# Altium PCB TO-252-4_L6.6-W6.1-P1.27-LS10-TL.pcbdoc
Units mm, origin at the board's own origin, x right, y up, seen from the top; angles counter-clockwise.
Board outline 23.63 x 19.35 mm, 2 copper layers (Top Layer, Bottom Layer), stack 0 mm thick; 1 components, 0 nets, 5 pads, 0 vias.
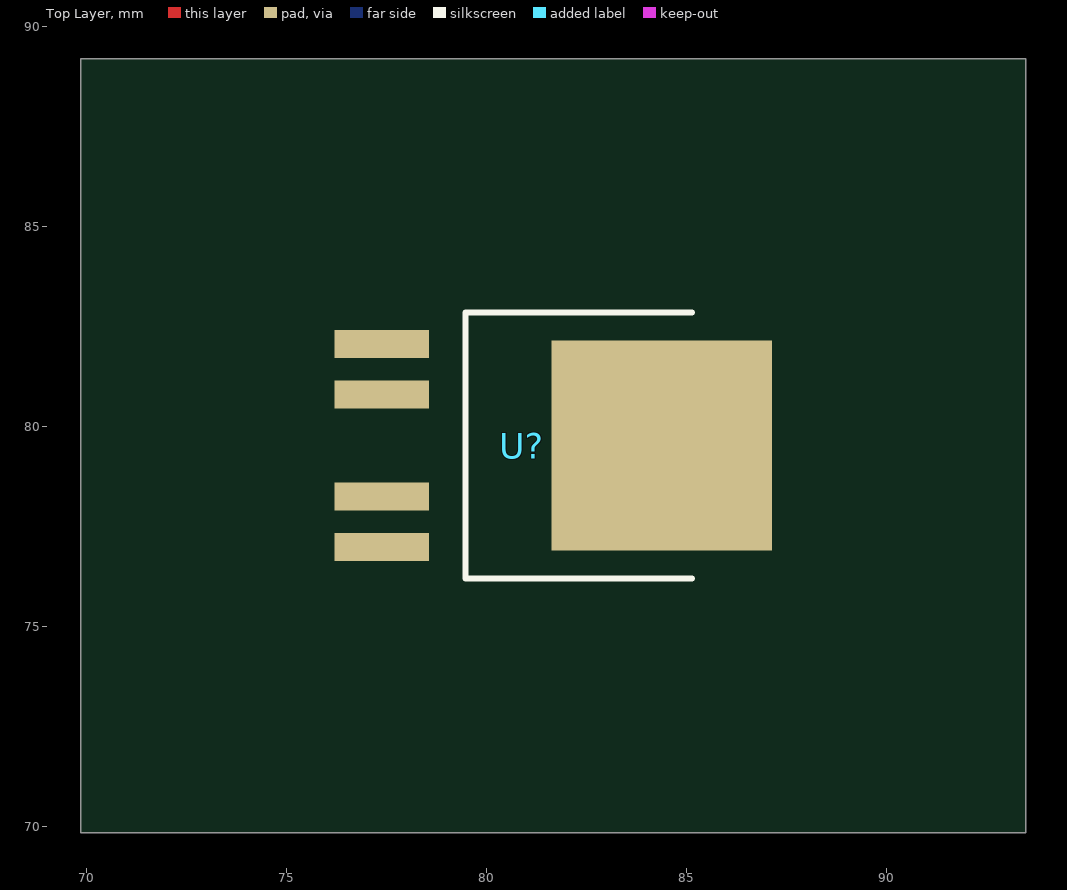
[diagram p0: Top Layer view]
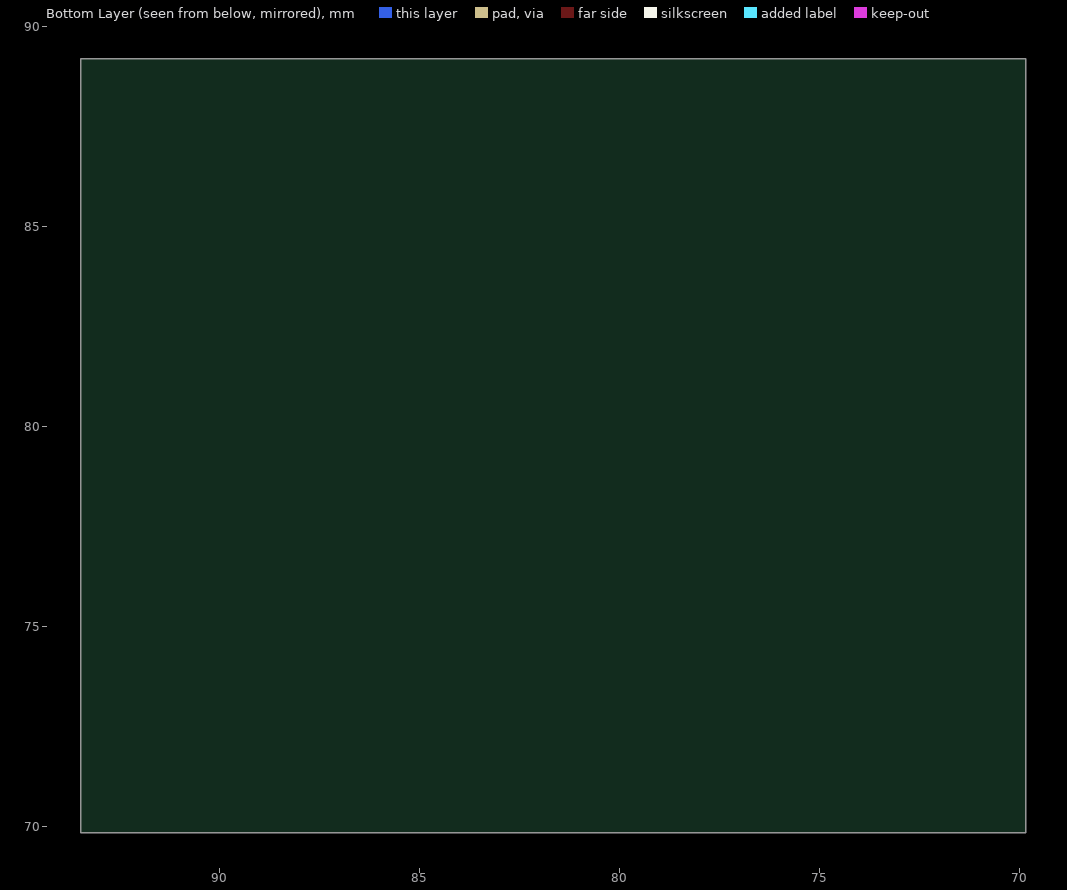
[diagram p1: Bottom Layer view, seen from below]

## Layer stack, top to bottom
Top Layer: signal copper (thickness not stored)
Bottom Layer: signal copper (thickness not stored)

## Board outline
93.484,69.85 69.85,69.85 69.85,89.202 93.484,89.202

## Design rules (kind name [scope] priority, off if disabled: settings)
PasteMaskExpansion "Paste Mask Expansion" [All] p1: expansion=0
SolderMaskExpansion "Solder Mask Expansion" [IsVia] p1: expansion=-25.4 istentingtop=TRUE
SolderMaskExpansion "Solder Mask Expansion" [All] p2: expansion=0.051 istentingtop=FALSE

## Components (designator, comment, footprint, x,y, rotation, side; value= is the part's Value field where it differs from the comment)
U? "" TO-252-4_L6.6-W6.1-P1.27-LS10-TL 80.878,79.526 r0 top

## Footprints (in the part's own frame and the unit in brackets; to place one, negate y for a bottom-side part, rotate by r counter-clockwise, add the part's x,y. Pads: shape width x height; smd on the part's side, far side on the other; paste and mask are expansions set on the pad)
TO-252-4_L6.6-W6.1-P1.27-LS10-TL [mm]
  rect 2.357x0.7 smd: 1(-3.5,2.54) 2(-3.5,1.27) 4(-3.5,-1.27) 5(-3.5,-2.54)
  rect 5.512x5.249 smd: 3(3.5,0)
  silkscreen extent -1.4,-3.33 4.25,3.33

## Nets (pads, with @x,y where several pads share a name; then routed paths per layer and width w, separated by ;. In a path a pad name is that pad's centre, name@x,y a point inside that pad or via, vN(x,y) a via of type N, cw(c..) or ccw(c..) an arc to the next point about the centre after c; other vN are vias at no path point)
pads on no net: U?.1 U?.2 U?.3 U?.4 U?.5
